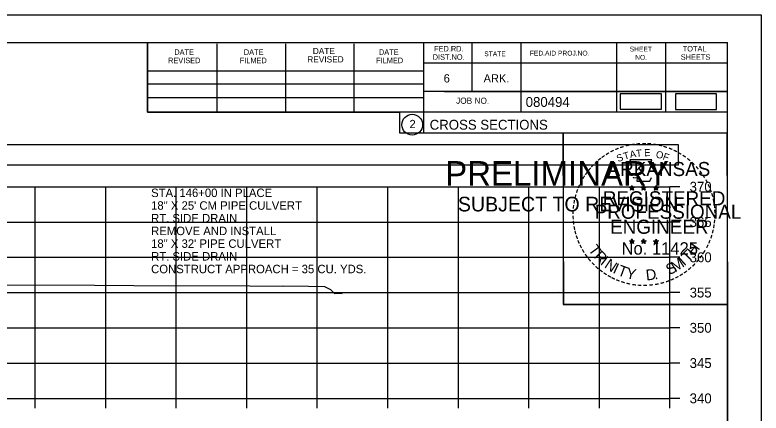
# Model space of a CAD drawing. Extents: x 1376273 to 1384221, y 378927 to 384592.
# Drawn here: x 1377114.9 to 1377220.7, y 382828.8 to 382885.2 of the extents above; entities that cross this region are included whole.
import ezdxf

# ---------------------------------------------------------------- set-up
doc = ezdxf.new("R2010")
doc.units = 0
for name, color, linetype in [('R_Axis', 7, 'Continuous'), ('R_Axis Annot', 7, 'Continuous'), ('R_Border', 7, 'Continuous'), ('R_Border PE', 7, 'Continuous'), ('R_Border Prem', 7, 'Continuous'), ('R_Drive', 7, 'Continuous'), ('R_Exist Surface', 7, 'Continuous'), ('R_Grid', 7, 'Continuous'), ('R_No Plot', 7, 'Continuous')]:
    doc.layers.add(name, color=color, linetype=linetype)

msp = doc.modelspace()

# ---------------------------------------------------------------- linework, layer by layer
at = {"layer": 'R_Axis'}
for p, q in [((1377207.77, 382830.87), (1377207.77, 382860.87)), ((1377209.17, 382860.87), (1377207.77, 382860.87)), ((1377209.17, 382855.87), (1377207.77, 382855.87)), ((1377209.17, 382850.87), (1377207.77, 382850.87)), ((1377209.17, 382845.87), (1377207.77, 382845.87)), ((1377209.17, 382840.87), (1377207.77, 382840.87)), ((1377209.17, 382835.87), (1377207.77, 382835.87)), ((1376907.77, 382830.87), (1377207.77, 382830.87)), ((1377117.77, 382829.47), (1377117.77, 382830.87)), ((1377127.77, 382829.47), (1377127.77, 382830.87)), ((1377137.77, 382829.47), (1377137.77, 382830.87)), ((1377147.77, 382829.47), (1377147.77, 382830.87)), ((1377157.77, 382829.47), (1377157.77, 382830.87)), ((1377167.77, 382829.47), (1377167.77, 382830.87)), ((1377177.77, 382829.47), (1377177.77, 382830.87)), ((1377187.77, 382829.47), (1377187.77, 382830.87)), ((1377197.77, 382829.47), (1377197.77, 382830.87)), ((1377207.77, 382829.47), (1377207.77, 382830.87)), ((1377209.17, 382830.87), (1377207.77, 382830.87))]:
    msp.add_line(p, q, dxfattribs=at)
at = {"layer": 'R_Axis Annot'}
msp.add_lwpolyline([(1376907.2, 382863.98), (1377209.01, 382863.98), (1377209.01, 382866.79), (1376907.2, 382866.79)], close=True, dxfattribs=at)
at = {"layer": 'R_Border'}
for p, q in [((1376899.77, 382881.33), (1377215.95, 382881.33)), ((1377133.69, 382871.45), (1377133.69, 382881.33)), ((1377143.55, 382871.45), (1377143.55, 382881.13)), ((1377153.31, 382871.45), (1377153.31, 382881.13)), ((1377162.99, 382871.45), (1377162.99, 382881.13)), ((1377172.85, 382881.33), (1377172.85, 382868.53)), ((1377179.69, 382881.33), (1377179.69, 382874.39)), ((1377186.63, 382881.33), (1377186.63, 382871.45)), ((1377200.21, 382881.33), (1377200.21, 382871.45)), ((1377207.15, 382881.33), (1377207.15, 382871.45)), ((1377215.95, 382675.87), (1377215.95, 382881.33)), ((1377215.95, 382878.41), (1377215.95, 382878.41)), ((1377215.95, 382878.39), (1377172.85, 382878.39)), ((1377133.69, 382877.31), (1377172.85, 382877.31)), ((1377133.69, 382875.45), (1377172.85, 382875.45)), ((1377215.95, 382874.39), (1377172.85, 382874.39)), ((1377175.81, 382874.39), (1377215.95, 382874.39)), ((1377133.69, 382871.45), (1377133.69, 382873.51)), ((1377133.69, 382873.51), (1377172.85, 382873.51)), ((1377215.95, 382871.45), (1377133.69, 382871.45)), ((1377172.85, 382868.53), (1377215.95, 382868.53))]:
    msp.add_line(p, q, dxfattribs=at)
msp.add_circle((1377171.23, 382869.67), 1.47, dxfattribs=at)
at = {"layer": 'R_Border PE'}
for p, q in [((1377202.03, 382860.79), (1377202.38, 382860.68)), ((1377202.03, 382860.79), (1377202.29, 382860.74)), ((1377202.03, 382860.79), (1377202.27, 382860.67)), ((1377202.17, 382860.38), (1377202.38, 382860.68)), ((1377202.17, 382860.38), (1377202.29, 382860.63)), ((1377202.17, 382860.38), (1377202.38, 382860.6)), ((1377202.38, 382861.04), (1377202.34, 382860.79)), ((1377202.38, 382860.68), (1377202.38, 382861.04)), ((1377202.38, 382861.04), (1377202.43, 382860.79)), ((1377202.73, 382860.79), (1377202.38, 382860.68)), ((1377202.59, 382860.38), (1377202.38, 382860.68)), ((1377202.59, 382860.38), (1377202.38, 382860.6)), ((1377202.73, 382860.79), (1377202.44, 382860.74)), ((1377202.59, 382860.38), (1377202.46, 382860.67)), ((1377202.73, 382860.79), (1377202.52, 382860.69)), ((1377203.7, 382860.79), (1377204.05, 382860.68)), ((1377203.7, 382860.79), (1377203.96, 382860.74)), ((1377203.7, 382860.79), (1377203.94, 382860.67)), ((1377203.84, 382860.38), (1377204.05, 382860.68)), ((1377203.84, 382860.38), (1377203.96, 382860.63)), ((1377203.84, 382860.38), (1377204.05, 382860.6)), ((1377204.05, 382861.04), (1377204.01, 382860.79)), ((1377204.05, 382860.68), (1377204.05, 382861.04)), ((1377204.05, 382861.04), (1377204.1, 382860.79)), ((1377204.4, 382860.79), (1377204.05, 382860.68)), ((1377204.26, 382860.38), (1377204.05, 382860.68)), ((1377204.26, 382860.38), (1377204.05, 382860.6)), ((1377204.4, 382860.79), (1377204.11, 382860.74)), ((1377204.26, 382860.38), (1377204.13, 382860.67)), ((1377204.4, 382860.79), (1377204.19, 382860.69)), ((1377205.47, 382860.78), (1377205.82, 382860.67)), ((1377205.47, 382860.78), (1377205.72, 382860.73)), ((1377205.47, 382860.78), (1377205.7, 382860.66)), ((1377205.6, 382860.37), (1377205.82, 382860.67)), ((1377205.6, 382860.37), (1377205.73, 382860.61)), ((1377205.6, 382860.37), (1377205.81, 382860.59)), ((1377205.82, 382861.03), (1377205.77, 382860.78)), ((1377206.03, 382860.37), (1377205.81, 382860.58)), ((1377205.82, 382860.67), (1377205.82, 382861.03)), ((1377205.82, 382861.03), (1377205.86, 382860.78)), ((1377206.16, 382860.78), (1377205.82, 382860.67)), ((1377206.03, 382860.37), (1377205.82, 382860.67)), ((1377206.16, 382860.78), (1377205.88, 382860.73)), ((1377206.03, 382860.37), (1377205.89, 382860.66)), ((1377206.16, 382860.78), (1377205.96, 382860.68)), ((1377202.03, 382853.22), (1377202.38, 382853.11)), ((1377202.03, 382853.22), (1377202.28, 382853.17)), ((1377202.03, 382853.22), (1377202.27, 382853.09)), ((1377202.16, 382852.81), (1377202.38, 382853.11)), ((1377202.16, 382852.81), (1377202.29, 382853.05)), ((1377202.16, 382852.81), (1377202.38, 382853.03)), ((1377202.38, 382853.47), (1377202.34, 382853.22)), ((1377202.38, 382853.11), (1377202.38, 382853.47)), ((1377202.38, 382853.47), (1377202.43, 382853.22)), ((1377202.72, 382853.22), (1377202.38, 382853.11)), ((1377202.59, 382852.81), (1377202.38, 382853.11)), ((1377202.59, 382852.81), (1377202.38, 382853.02)), ((1377202.72, 382853.22), (1377202.44, 382853.17)), ((1377202.59, 382852.81), (1377202.45, 382853.1)), ((1377202.72, 382853.22), (1377202.52, 382853.11)), ((1377203.7, 382853.22), (1377204.05, 382853.11)), ((1377203.7, 382853.22), (1377203.95, 382853.17)), ((1377203.7, 382853.22), (1377203.93, 382853.09)), ((1377203.83, 382852.81), (1377204.05, 382853.11)), ((1377203.83, 382852.81), (1377203.96, 382853.05)), ((1377203.83, 382852.81), (1377204.04, 382853.03)), ((1377204.05, 382853.47), (1377204.01, 382853.22)), ((1377204.26, 382852.81), (1377204.04, 382853.02)), ((1377204.05, 382853.11), (1377204.05, 382853.47)), ((1377204.05, 382853.47), (1377204.1, 382853.22)), ((1377204.39, 382853.22), (1377204.05, 382853.11)), ((1377204.26, 382852.81), (1377204.05, 382853.11)), ((1377204.39, 382853.22), (1377204.11, 382853.17)), ((1377204.26, 382852.81), (1377204.12, 382853.1)), ((1377204.39, 382853.22), (1377204.19, 382853.11)), ((1377205.46, 382853.21), (1377205.81, 382853.1)), ((1377205.46, 382853.21), (1377205.72, 382853.16)), ((1377205.46, 382853.21), (1377205.7, 382853.08)), ((1377205.6, 382852.8), (1377205.81, 382853.1)), ((1377205.6, 382852.8), (1377205.72, 382853.04)), ((1377205.6, 382852.8), (1377205.81, 382853.02)), ((1377205.81, 382853.46), (1377205.77, 382853.21)), ((1377205.81, 382853.1), (1377205.81, 382853.46)), ((1377205.81, 382853.46), (1377205.86, 382853.21)), ((1377206.16, 382853.21), (1377205.81, 382853.1)), ((1377206.03, 382852.8), (1377205.81, 382853.1)), ((1377206.16, 382853.21), (1377205.87, 382853.16)), ((1377206.03, 382852.8), (1377205.89, 382853.09)), ((1377206.16, 382853.21), (1377205.96, 382853.1)), ((1377206.03, 382852.8), (1377205.81, 382853.01))]:
    msp.add_line(p, q, dxfattribs=at)
for points in [[(1377202.07, 382864.67), (1377202.34, 382863.84)], [(1377205.58, 382863.75), (1377205.73, 382864.03), (1377205.04, 382864.01), (1377205.19, 382864.67), (1377202.07, 382864.67)], [(1377202.57, 382862.24), (1377202.57, 382862.16), (1377203.13, 382862.14), (1377203.07, 382861.67), (1377204.94, 382861.67), (1377205.15, 382862.2)], [(1377202.38, 382861.04), (1377202.59, 382860.38), (1377202.03, 382860.79), (1377202.73, 382860.79), (1377202.17, 382860.38), (1377202.38, 382861.04)], [(1377204.05, 382861.04), (1377204.26, 382860.38), (1377203.7, 382860.79), (1377204.4, 382860.79), (1377203.84, 382860.38), (1377204.05, 382861.04)], [(1377205.82, 382861.03), (1377206.03, 382860.37), (1377205.47, 382860.78), (1377206.16, 382860.78), (1377205.6, 382860.37), (1377205.82, 382861.03)], [(1377202.38, 382853.47), (1377202.59, 382852.81), (1377202.03, 382853.22), (1377202.72, 382853.22), (1377202.16, 382852.81), (1377202.38, 382853.47)], [(1377204.05, 382853.47), (1377204.26, 382852.81), (1377203.7, 382853.22), (1377204.39, 382853.22), (1377203.83, 382852.81), (1377204.05, 382853.47)], [(1377205.81, 382853.46), (1377206.03, 382852.8), (1377205.46, 382853.21), (1377206.16, 382853.21), (1377205.6, 382852.8), (1377205.81, 382853.46)]]:
    msp.add_lwpolyline(points, dxfattribs=at)
for centre, radius in [((1377202.38, 382860.68), 0.172), ((1377202.38, 382860.68), 0.145), ((1377202.38, 382860.68), 0.116), ((1377202.38, 382860.68), 0.0991), ((1377202.38, 382860.68), 0.0747), ((1377202.38, 382860.68), 0.0495), ((1377202.38, 382860.68), 0.0296), ((1377204.05, 382860.68), 0.172), ((1377204.05, 382860.68), 0.145), ((1377204.05, 382860.68), 0.116), ((1377204.05, 382860.68), 0.0991), ((1377204.05, 382860.68), 0.0747), ((1377204.05, 382860.68), 0.0495), ((1377204.05, 382860.68), 0.0296), ((1377205.81, 382860.67), 0.172), ((1377205.81, 382860.67), 0.145), ((1377205.81, 382860.67), 0.116), ((1377205.81, 382860.67), 0.0991), ((1377205.81, 382860.67), 0.0747), ((1377205.81, 382860.67), 0.0495), ((1377205.81, 382860.67), 0.0296), ((1377202.38, 382853.1), 0.172), ((1377202.38, 382853.1), 0.145), ((1377202.38, 382853.1), 0.116), ((1377202.38, 382853.1), 0.0991), ((1377202.38, 382853.1), 0.0747), ((1377202.38, 382853.1), 0.0495), ((1377202.38, 382853.1), 0.0296), ((1377204.05, 382853.1), 0.172), ((1377204.05, 382853.1), 0.145), ((1377204.05, 382853.1), 0.116), ((1377204.05, 382853.1), 0.0991), ((1377204.05, 382853.1), 0.0747), ((1377204.05, 382853.1), 0.0495), ((1377204.05, 382853.1), 0.0296), ((1377205.81, 382853.09), 0.172), ((1377205.81, 382853.09), 0.145), ((1377205.81, 382853.09), 0.116), ((1377205.81, 382853.09), 0.0991), ((1377205.81, 382853.09), 0.0747), ((1377205.81, 382853.09), 0.0495), ((1377205.81, 382853.09), 0.0296)]:
    msp.add_circle(centre, radius, dxfattribs=at)
at = {"layer": 'R_Drive'}
for points in [[(1377200.73, 382871.85), (1377206.56, 382871.85), (1377206.56, 382874.04), (1377200.73, 382874.04)], [(1377208.55, 382871.83), (1377214.39, 382871.83), (1377214.39, 382874.02), (1377208.55, 382874.02)]]:
    msp.add_lwpolyline(points, close=True, dxfattribs=at)
at = {"layer": 'R_Exist Surface'}
msp.add_lwpolyline([(1377111.54, 382846.96), (1377126.19, 382846.9), (1377131.74, 382846.86), (1377148.22, 382846.8), (1377152.85, 382846.76), (1377153.03, 382846.81), (1377156.5, 382846.79), (1377158.78, 382846.74), (1377159.63, 382846.28), (1377160.2, 382845.74), (1377160.73, 382845.76), (1377161.29, 382845.73)], dxfattribs=at)
at = {"layer": 'R_Grid'}
for p, q in [((1376907.77, 382860.87), (1377207.77, 382860.87)), ((1377117.77, 382830.87), (1377117.77, 382860.87)), ((1377127.77, 382830.87), (1377127.77, 382860.87)), ((1377137.77, 382830.87), (1377137.77, 382860.87)), ((1377147.77, 382830.87), (1377147.77, 382860.87)), ((1377157.77, 382830.87), (1377157.77, 382860.87)), ((1377167.77, 382830.87), (1377167.77, 382860.87)), ((1377177.77, 382830.87), (1377177.77, 382860.87)), ((1377187.77, 382830.87), (1377187.77, 382860.87)), ((1377197.77, 382830.87), (1377197.77, 382860.87)), ((1377207.77, 382830.87), (1377207.77, 382860.87)), ((1376907.77, 382855.87), (1377207.77, 382855.87)), ((1376907.77, 382850.87), (1377207.77, 382850.87)), ((1376907.77, 382845.87), (1377207.77, 382845.87)), ((1376907.77, 382840.87), (1377207.77, 382840.87)), ((1376907.77, 382835.87), (1377207.77, 382835.87)), ((1376907.77, 382830.87), (1377207.77, 382830.87))]:
    msp.add_line(p, q, dxfattribs=at)
at = {"layer": 'R_No Plot'}
for p, q in [((1376887.37, 382885.23), (1377220.7, 382885.23)), ((1377191.98, 382846.08), (1377191.98, 382846.08))]:
    msp.add_line(p, q, dxfattribs=at)
for points in [[(1376887.36, 382885.23), (1377220.7, 382885.23), (1377220.7, 382671.89), (1376887.36, 382671.89)], [(1377133.69, 382881.33), (1377133.69, 382871.45), (1377169.42, 382871.45), (1377169.42, 382868.53), (1377192.62, 382868.53), (1377192.62, 382844.2), (1377215.95, 382844.2), (1377215.95, 382675.87), (1376899.77, 382675.87), (1376899.77, 382881.33)], [(1377192.62, 382868.53), (1377215.83, 382868.53), (1377215.95, 382844.2), (1377192.74, 382844.2)]]:
    msp.add_lwpolyline(points, close=True, dxfattribs=at)

# ---------------------------------------------------------------- texts
at = {"layer": 'R_Axis Annot'}
for s, p in [('370', (1377210.57, 382860.17)), ('365', (1377210.57, 382855.17)), ('360', (1377210.57, 382850.17)), ('355', (1377210.57, 382845.17)), ('350', (1377210.57, 382840.17)), ('345', (1377210.57, 382835.17)), ('340', (1377210.57, 382830.17))]:
    msp.add_text(s, height=1.4, dxfattribs=at).set_placement(p)
at = {"layer": 'R_Border'}
for s, height, p in [('DATE', 0.879, (1377157.13, 382879.67)), ('FED.RD.', 0.782, (1377174.33, 382880.05)), ('SHEET', 0.684, (1377202.07, 382880.05)), ('TOTAL', 0.782, (1377209.59, 382880.05)), ('DATE', 0.782, (1377137.49, 382879.57)), ('DATE', 0.782, (1377147.35, 382879.57)), ('DATE', 0.782, (1377166.51, 382879.57)), ('DIST.NO.', 0.782, (1377174.13, 382878.87)), ('STATE', 0.684, (1377181.45, 382879.37)), ('FED.AID PROJ.NO.', 0.684, (1377187.91, 382879.47)), ('NO.', 0.684, (1377202.85, 382878.87)), ('SHEETS', 0.782, (1377209.31, 382878.87)), ('REVISED', 0.782, (1377136.61, 382878.39)), ('FILMED', 0.782, (1377146.77, 382878.39)), ('REVISED', 0.879, (1377156.35, 382878.49)), ('FILMED', 0.782, (1377166.11, 382878.39)), ('6', 1.17, (1377175.69, 382875.65)), ('ARK.', 1.172, (1377181.35, 382875.65)), ('JOB NO.', 0.879, (1377177.45, 382872.63)), ('080494', 1.4, (1377187.32, 382872.19)), ('2', 1.17, (1377170.85, 382869.18)), ('CROSS SECTIONS', 1.4, (1377173.71, 382868.96))]:
    msp.add_text(s, height=height, rotation=360, dxfattribs=at).set_placement(p)
at = {"layer": 'R_Border PE'}
for s, height, rotation, p in [('-', 1.6, 13.6301, (1377201.57, 382866.04)), ('-', 1.6, 10.2193, (1377202.25, 382866.2)), ('-', 1.6, 5.8968, (1377202.98, 382866.31)), ('-', 1.6, 0.1862, (1377203.75, 382866.38)), ('-', 1.6, 357.743, (1377204.47, 382866.37)), ('-', 1.6, 352.1617, (1377205.22, 382866.31)), ('-', 1.6, 347.2049, (1377205.94, 382866.2)), ('-', 1.6, 34.0636, (1377198.96, 382864.84)), ('-', 1.6, 28.7918, (1377199.55, 382865.21)), ('-', 1.6, 24.3072, (1377200.19, 382865.53)), ('-', 1.6, 19.1761, (1377200.82, 382865.79)), ('T', 1, 16.4036, (1377201.34, 382864.68)), ('A', 1, 11.2132, (1377202.17, 382864.93)), ('T', 1, 6.0228, (1377203.02, 382865.09)), ('E', 1, 0.8323, (1377204.12, 382865.2)), ('O', 1, 350.4515, (1377205.73, 382864.99)), ('-', 1.6, 342.3362, (1377206.57, 382866.04)), ('-', 1.6, 337.8551, (1377207.31, 382865.82)), ('-', 1.6, 334.1211, (1377207.94, 382865.55)), ('-', 1.6, 329.6409, (1377208.52, 382865.26)), ('-', 1.6, 38.9507, (1377197.9, 382864.07)), ('-', 1.6, 36.2317, (1377198.38, 382864.44)), ('S', 1, 21.594, (1377200.43, 382864.35)), ('F', 1, 340.0707, (1377206.68, 382864.77)), ('-', 1.6, 325.8627, (1377209.16, 382864.9)), ('-', 1.6, 320.5297, (1377209.77, 382864.48)), ('-', 1.6, 50.6142, (1377196.62, 382862.68)), ('-', 1.6, 48.423, (1377197.02, 382863.17)), ('-', 1.6, 42.9622, (1377197.47, 382863.65)), ('ARKANSAS', 2, 360, (1377198.93, 382862.38)), ('-', 1.6, 315.5786, (1377210.37, 382863.99)), ('-', 1.6, 309.8797, (1377210.94, 382863.44)), ('-', 1.6, 54.2325, (1377196.21, 382862.12)), ('-', 1.6, 306.6522, (1377211.46, 382862.84)), ('-', 1.4, 303.6753, (1377211.95, 382862.27)), ('-', 1.6, 62.8713, (1377195.57, 382860.98)), ('-', 1.6, 58.0706, (1377195.88, 382861.59)), ('-', 1.6, 299.6684, (1377212.27, 382861.66)), ('-', 1.6, 72.3945, (1377195.09, 382859.74)), ('-', 1.6, 67.7743, (1377195.31, 382860.37)), ('DWB', 0.01, 360, (1377202.37, 382860.67)), ('DWB', 0.01, 360, (1377204.04, 382860.67)), ('DWB', 0.01, 360, (1377205.8, 382860.66)), ('-', 1.6, 294.6628, (1377212.59, 382861.05)), ('-', 1.6, 290.5728, (1377212.85, 382860.47)), ('-', 1.6, 75.461, (1377194.89, 382859.02)), ('REGISTERED', 2, 360, (1377198.25, 382858.23)), ('-', 1.6, 285.1233, (1377213.08, 382859.89)), ('-', 1.6, 81.2013, (1377194.76, 382858.31)), ('PROFESSIONAL', 2, 360, (1377197.1, 382856.33)), ('-', 1.6, 280.5493, (1377213.28, 382859.15)), ('-', 1.6, 276.5962, (1377213.44, 382858.38)), ('-', 1.6, 89.0622, (1377194.66, 382856.92)), ('-', 1.6, 85.1863, (1377194.68, 382857.62)), ('-', 1.6, 274.3301, (1377213.5, 382857.66)), ('-', 1.6, 94.1959, (1377194.69, 382856.19)), ('ENGINEER', 2, 360, (1377199.29, 382854.2)), ('-', 1.6, 263.5172, (1377213.52, 382856.36)), ('-', 1.6, 269.9407, (1377213.54, 382857.03)), ('-', 1.6, 98.9479, (1377194.77, 382855.52)), ('-', 1.6, 101.7149, (1377194.9, 382854.79)), ('-', 1.6, 260.9953, (1377213.45, 382855.71)), ('-', 1.6, 105.4578, (1377195.06, 382854.2)), ('-', 1.6, 255.7626, (1377213.34, 382855.03)), ('-', 1.6, 109.0874, (1377195.28, 382853.57)), ('-', 1.6, 114.0643, (1377195.53, 382852.97)), ('No. 11425', 1.757, 360, (1377200.91, 382851.25)), ('DWB', 0.01, 360, (1377202.36, 382853.1)), ('DWB', 0.01, 360, (1377204.03, 382853.1)), ('DWB', 0.01, 360, (1377205.8, 382853.09)), ('-', 1.6, 247.8887, (1377212.93, 382853.64)), ('-', 1.6, 252.8681, (1377213.16, 382854.31)), ('-', 1.6, 115.7289, (1377195.84, 382852.35)), ('-', 1.6, 120.4471, (1377196.19, 382851.77)), ('T', 1.54, 306.0406, (1377196.14, 382851.94)), ('T', 1.54, 46.6444, (1377210.37, 382850.04)), ('H', 1.54, 54.6088, (1377211.26, 382850.98)), ('-', 1.6, 244.6197, (1377212.67, 382853.01)), ('-', 1.6, 125.8934, (1377196.6, 382851.2)), ('R', 1.54, 314.005, (1377196.9, 382850.9)), ('I', 1.54, 321.9694, (1377197.8, 382849.96)), ('I', 1.54, 42.1136, (1377209.81, 382849.56)), ('-', 1.6, 233.8452, (1377211.88, 382851.6)), ('-', 1.6, 239.0712, (1377212.28, 382852.26)), ('-', 1.6, 130.7181, (1377197.06, 382850.65)), ('-', 1.6, 134.2238, (1377197.58, 382850.11)), ('N', 1.54, 326.5002, (1377198.37, 382849.49)), ('I', 1.54, 335.3603, (1377199.57, 382848.71)), ('S', 1.54, 26.9312, (1377207.68, 382848.31)), ('M', 1.54, 32.6563, (1377208.52, 382848.71)), ('-', 1.6, 225.7653, (1377210.97, 382850.47)), ('-', 1.6, 231.2538, (1377211.45, 382851.04)), ('-', 1.6, 138.9338, (1377198.1, 382849.64)), ('-', 1.6, 144.6463, (1377198.66, 382849.24)), ('T', 1.54, 339.8912, (1377200.24, 382848.38)), ('Y', 1.54, 347.8556, (1377201.45, 382847.93)), ('D', 1.54, 6.3969, (1377204.44, 382847.57)), ('-', 1.6, 215.7363, (1377209.9, 382849.49)), ('-', 1.6, 221.0851, (1377210.44, 382849.97)), ('-', 1.6, 148.0898, (1377199.22, 382848.87)), ('-', 1.6, 151.5704, (1377199.8, 382848.54)), ('-', 1.6, 154.6002, (1377200.32, 382848.29)), ('-', 1.6, 158.5612, (1377200.94, 382848.04)), ('.', 1.54, 13.7642, (1377205.63, 382847.7)), ('-', 1.6, 204.2516, (1377208.18, 382848.44)), ('-', 1.6, 207.3568, (1377208.8, 382848.76)), ('-', 1.6, 212.2491, (1377209.36, 382849.11)), ('-', 1.6, 162.7983, (1377201.63, 382847.83)), ('-', 1.6, 167.5555, (1377202.35, 382847.66)), ('-', 1.6, 173.1155, (1377203.12, 382847.55)), ('-', 1.6, 176.5183, (1377203.87, 382847.5)), ('-', 1.6, 181.5918, (1377204.61, 382847.52)), ('-', 1.6, 185.8167, (1377205.42, 382847.6)), ('-', 1.6, 191.2858, (1377206.15, 382847.73)), ('-', 1.6, 195.4743, (1377206.88, 382847.93)), ('-', 1.6, 200.7184, (1377207.56, 382848.17))]:
    msp.add_text(s, height=height, rotation=rotation, dxfattribs=at).set_placement(p)
at = {"layer": 'R_Border Prem'}
for s, height, p in [('PRELIMINARY', 3.5, (1377175.9, 382861)), ('DWB', 0.01, (1377176.64, 382862.85)), ('SUBJECT TO REVISION', 2.0751, (1377177.71, 382857.37))]:
    msp.add_text(s, height=height, rotation=360, dxfattribs=at).set_placement(p)
at = {"layer": 'R_Drive'}
for s, p in [('STA. 146+00 IN PLACE', (1377134.2, 382859.41)), ('18" X 25\' CM PIPE CULVERT', (1377134.2, 382857.61)), ('RT. SIDE DRAIN', (1377134.2, 382855.81)), ('REMOVE AND INSTALL', (1377134.2, 382854.01)), ('18" X 32\' PIPE CULVERT', (1377134.2, 382852.21)), ('RT. SIDE DRAIN', (1377134.2, 382850.41)), ('CONSTRUCT APPROACH = 35 CU. YDS.', (1377134.2, 382848.61))]:
    msp.add_text(s, height=1.2, dxfattribs=at).set_placement(p)

doc.saveas('drawing.dxf')
